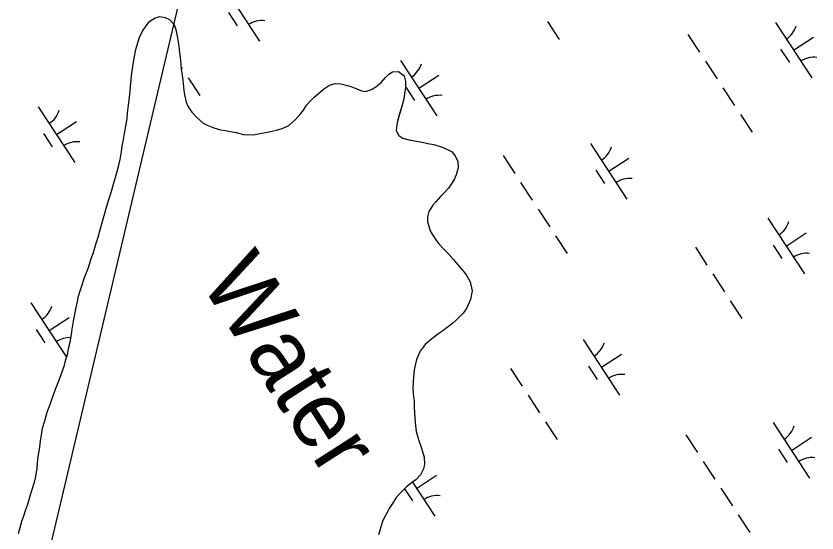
# Model space of a CAD drawing. Extents: x 3945642 to 3966284, y 206476 to 228921.
# Drawn here: x 3961600 to 3962203, y 213839 to 214228 of the extents above; entities that cross this region are included whole.
import ezdxf

# ---------------------------------------------------------------- set-up
doc = ezdxf.new("R2010")
doc.units = 0
for name, color, linetype in [('V-RIVR-IDEN', 7, 'Continuous'), ('V-TOPO-SHOR', 7, 'Continuous'), ('V-UTIL-LINE', 7, 'Continuous'), ('V-WETL-SWMP', 7, 'Continuous')]:
    doc.layers.add(name, color=color, linetype=linetype)

msp = doc.modelspace()

# ---------------------------------------------------------------- linework, layer by layer
at = {"layer": 'V-TOPO-SHOR'}
for points in [[(3961601.81, 213838.43), (3961603.06, 213842.74), (3961604.45, 213847.59), (3961605.55, 213850.95), (3961607.48, 213856.48), (3961608.87, 213860.38), (3961610.67, 213866.58), (3961612.05, 213870.75), (3961613.85, 213877.09), (3961614.83, 213881.13), (3961615.83, 213887.6), (3961616.55, 213894.21), (3961617.98, 213903.66), (3961618.55, 213908.11), (3961619.4, 213914.04), (3961619.97, 213917.68), (3961621.36, 213922.4), (3961622.74, 213926.98), (3961623.71, 213930.48), (3961625.5, 213934.79), (3961626.75, 213938.43), (3961628.82, 213944.21), (3961630.33, 213948.26), (3961632.68, 213954.45), (3961634.33, 213958.62), (3961636.54, 213965.08), (3961637.65, 213969.26), (3961638.76, 213972.9), (3961639.88, 213978.56), (3961640.72, 213982.34), (3961641.71, 213988.14), (3961642.42, 213992.05), (3961643.27, 213997.98), (3961643.98, 214001.89), (3961644.96, 214007.28), (3961646.22, 214012.54), (3961646.92, 214016.18), (3961648.58, 214021.7), (3961649.83, 214025.34), (3961651.63, 214030.86), (3961654.52, 214038.54), (3961656.59, 214045.14), (3961658.25, 214049.71), (3961660.47, 214056.85), (3961661.85, 214061.17), (3961663.66, 214067.9), (3961664.91, 214072.35), (3961666.85, 214079.22), (3961668.23, 214083.8), (3961670.17, 214090.4), (3961671.56, 214094.85), (3961673.36, 214101.05), (3961675.3, 214107.24), (3961677.52, 214115.46), (3961678.37, 214119.77), (3961679.49, 214125.71), (3961679.93, 214129.76), (3961681.05, 214134.88), (3961682.04, 214140.81), (3961682.75, 214144.72), (3961683.6, 214150.52), (3961684.03, 214154.57), (3961684.76, 214160.64), (3961685.33, 214164.69), (3961685.91, 214170.76), (3961686.21, 214174.67), (3961686.66, 214179.26), (3961686.95, 214182.63), (3961687.95, 214189.64), (3961688.94, 214195.98), (3961690.34, 214202.59), (3961692.01, 214208.52), (3961692.98, 214211.61), (3961695.17, 214216.33), (3961697.91, 214220.35), (3961700.9, 214223.71), (3961704.7, 214226.24), (3961708.22, 214227.3), (3961712.4, 214226.59), (3961715.63, 214224.95), (3961719.11, 214221.27), (3961720.43, 214217.48), (3961721.34, 214212.61), (3961722.5, 214204.91), (3961723, 214199.91)], [(3961723, 214199.91), (3961723.52, 214196.53), (3961724.01, 214191.39), (3961724.39, 214188.02), (3961725.03, 214183.02), (3961725.54, 214179.5), (3961726.05, 214174.5), (3961726.43, 214171.39), (3961727.07, 214167.34), (3961728.12, 214162.87), (3961729.44, 214159.89), (3961732.38, 214155.41), (3961736.26, 214151.2), (3961740.82, 214147.11), (3961743.92, 214145.47), (3961749.03, 214143.54), (3961753.88, 214142.15), (3961757.79, 214141.45), (3961762.78, 214140.46), (3961765.75, 214139.9), (3961771.41, 214138.64), (3961778.97, 214138.31), (3961782.48, 214138.96), (3961787.89, 214140), (3961791.54, 214140.78), (3961796.28, 214141.83), (3961800.47, 214143.15), (3961805.35, 214145.4), (3961810.52, 214149.68), (3961814.6, 214154.24), (3961816.51, 214156.8), (3961818.84, 214160.69), (3961821.97, 214164.18), (3961824.42, 214166.73), (3961827.81, 214169.4), (3961831.48, 214172.61), (3961835.96, 214175.55), (3961840.3, 214177), (3961844.62, 214176.56), (3961849.74, 214175.31), (3961852.97, 214174.34), (3961856.6, 214172.82), (3961860.1, 214171.31), (3961863.07, 214170.75), (3961867.81, 214172.33), (3961871.06, 214174.33), (3961874.87, 214177.68), (3961878.14, 214181.44), (3961880.72, 214183.98), (3961883.44, 214185.72), (3961888.03, 214185.82), (3961892.19, 214182.68), (3961893.38, 214178.62), (3961893.2, 214173.62), (3961892.63, 214169.58), (3961892.2, 214166.34), (3961890.81, 214160.68), (3961888.87, 214154.08), (3961886.92, 214147.48), (3961886.2, 214141.54), (3961888.2, 214137.75), (3961891.16, 214135.83), (3961896.01, 214134.45), (3961902.75, 214133.18), (3961907.06, 214132.47), (3961910.03, 214131.77), (3961914.61, 214131.06), (3961921.75, 214128.85), (3961927.81, 214125.7), (3961930.75, 214122.43), (3961932.74, 214118.23), (3961932.84, 214113.37), (3961931.45, 214108.25), (3961929.94, 214104.62), (3961928.3, 214101.93), (3961925.57, 214098.03), (3961922.16, 214094.28), (3961919.58, 214091.87), (3961916.04, 214087.98), (3961913.86, 214085.43), (3961910.85, 214080.59), (3961909.88, 214076.68), (3961909.85, 214072.77), (3961911.82, 214066.14), (3961913.42, 214063.42), (3961916.23, 214059.35), (3961918.5, 214056.36), (3961922.25, 214052.15), (3961925.06, 214049.16), (3961929.07, 214044.67), (3961931.62, 214041.68), (3961934.03, 214038.96), (3961937.37, 214035.02), (3961939.51, 214032.17), (3961941.91, 214027.56), (3961943.61, 214020.93), (3961942.35, 214014.46), (3961940.56, 214010.29), (3961939.19, 214007.6), (3961936.6, 214004.1), (3961931.42, 213998.74)], [(3961931.42, 213998.74), (3961928.84, 213996.6), (3961924.63, 213993.26), (3961921.37, 213990.85), (3961918.39, 213988.85), (3961914.04, 213985.64), (3961911.59, 213983.5), (3961908.2, 213980.56), (3961904.24, 213975.59), (3961901.62, 213969.13), (3961900.79, 213966.03), (3961899.81, 213961.31), (3961899.23, 213956.05), (3961899.07, 213952.54), (3961898.9, 213947.68), (3961899.39, 213941.2), (3961899.77, 213938.09), (3961899.87, 213933.49), (3961899.97, 213929.04), (3961900.45, 213921.75), (3961901.35, 213914.99), (3961903.06, 213909.17), (3961905.3, 213902.67), (3961907.27, 213895.77), (3961907.51, 213890.63), (3961906.94, 213886.99), (3961904.47, 213882.42), (3961901.07, 213878.8), (3961898.62, 213876.93), (3961894.14, 213873.45), (3961889.93, 213869.44), (3961886.38, 213865.41), (3961883.38, 213860.98), (3961880.92, 213857.08), (3961879.55, 213854.26), (3961877.35, 213850.09), (3961875.98, 213847.26), (3961874.74, 213843.36), (3961872.94, 213837.29)]]:
    msp.add_lwpolyline(points, dxfattribs=at)
at = {"layer": 'V-UTIL-LINE'}
msp.add_lwpolyline([(3961854.02, 214793.94), (3961386.17, 212816.75)], dxfattribs=at)
at = {"layer": 'V-WETL-SWMP'}
for p, q in [((3961755.97, 214250.5), (3961783.37, 214208.67)), ((3961704.7, 214226.24), (3961708.22, 214227.3)), ((3961708.22, 214227.3), (3961712.4, 214226.59)), ((3961759.93, 214230.38), (3961766.5, 214220.34)), ((3961697.91, 214220.36), (3961700.9, 214223.71)), ((3961700.9, 214223.71), (3961704.7, 214226.24)), ((3961712.4, 214226.59), (3961715.63, 214224.95)), ((3961715.63, 214224.95), (3961719.11, 214221.27)), ((3961719.11, 214221.27), (3961720.43, 214217.48)), ((3962000.3, 214223.43), (3962009.07, 214210.05)), ((3962171.77, 214222.88), (3962199.16, 214181.06)), ((3961692.98, 214211.62), (3961695.18, 214216.33)), ((3961695.18, 214216.33), (3961697.91, 214220.36)), ((3961720.43, 214217.48), (3961721.34, 214212.61)), ((3961692.01, 214208.52), (3961692.98, 214211.62)), ((3961721.34, 214212.61), (3961722.5, 214204.91)), ((3962105.97, 214213.76), (3962114.74, 214200.37)), ((3962185.46, 214201.97), (3962200.52, 214211.83)), ((3961690.34, 214202.59), (3961692.01, 214208.52)), ((3961722.5, 214204.91), (3961723, 214199.91)), ((3962175.72, 214202.76), (3962182.3, 214192.72)), ((3961688.94, 214195.98), (3961690.34, 214202.59)), ((3961723, 214199.91), (3961723.51, 214196.53)), ((3961687.95, 214189.65), (3961688.94, 214195.98)), ((3961723.51, 214196.53), (3961724.01, 214191.39)), ((3961724.01, 214191.39), (3961724.39, 214188.02)), ((3961889.55, 214194.27), (3961916.95, 214152.45)), ((3962119.12, 214193.68), (3962127.89, 214180.3)), ((3961686.95, 214182.63), (3961687.95, 214189.65)), ((3961724.24, 214189.37), (3961725.24, 214187.84)), ((3961724.39, 214188.02), (3961725.03, 214183.02)), ((3961880.72, 214183.98), (3961883.44, 214185.72)), ((3961883.44, 214185.72), (3961888.03, 214185.82)), ((3961888.03, 214185.82), (3961892.19, 214182.68)), ((3961686.21, 214174.67), (3961686.65, 214179.26)), ((3961686.65, 214179.26), (3961686.95, 214182.63)), ((3961725.03, 214183.02), (3961725.54, 214179.5)), ((3961725.54, 214179.5), (3961726.04, 214174.5)), ((3961729.63, 214181.15), (3961738.4, 214167.76)), ((3961874.87, 214177.68), (3961878.14, 214181.44)), ((3961878.14, 214181.44), (3961880.72, 214183.98)), ((3961892.19, 214182.68), (3961893.38, 214178.62)), ((3961893.38, 214178.62), (3961893.2, 214173.62)), ((3961903.25, 214173.36), (3961918.31, 214183.22)), ((3961685.91, 214170.76), (3961686.21, 214174.67)), ((3961726.04, 214174.5), (3961726.43, 214171.39)), ((3961827.82, 214169.4), (3961831.49, 214172.61)), ((3961831.49, 214172.61), (3961835.96, 214175.55)), ((3961835.96, 214175.55), (3961840.3, 214177)), ((3961840.3, 214177), (3961844.61, 214176.56)), ((3961844.61, 214176.56), (3961849.74, 214175.31)), ((3961849.74, 214175.31), (3961852.97, 214174.34)), ((3961852.97, 214174.34), (3961856.6, 214172.83)), ((3961856.6, 214172.83), (3961860.1, 214171.31)), ((3961867.81, 214172.33), (3961871.06, 214174.33)), ((3961871.06, 214174.33), (3961874.87, 214177.68)), ((3961893.2, 214173.62), (3961892.63, 214169.58)), ((3961893.51, 214174.15), (3961900.09, 214164.11)), ((3962132.27, 214173.6), (3962141.04, 214160.22)), ((3961685.33, 214164.69), (3961685.91, 214170.76)), ((3961726.43, 214171.39), (3961727.07, 214167.34)), ((3961727.07, 214167.34), (3961728.12, 214162.87)), ((3961821.97, 214164.18), (3961824.42, 214166.73)), ((3961824.42, 214166.73), (3961827.82, 214169.4)), ((3961860.1, 214171.31), (3961863.07, 214170.75)), ((3961863.07, 214170.75), (3961867.81, 214172.33)), ((3961892.63, 214169.58), (3961892.2, 214166.34)), ((3961684.03, 214154.57), (3961684.76, 214160.64)), ((3961684.76, 214160.64), (3961685.33, 214164.69)), ((3961728.12, 214162.87), (3961729.44, 214159.89)), ((3961816.51, 214156.79), (3961818.84, 214160.69)), ((3961818.84, 214160.69), (3961821.97, 214164.18)), ((3961890.81, 214160.68), (3961886.93, 214147.48)), ((3961892.2, 214166.34), (3961890.81, 214160.68)), ((3961616.83, 214159.35), (3961644.23, 214117.52)), ((3961683.6, 214150.52), (3961684.03, 214154.57)), ((3961729.44, 214159.89), (3961732.38, 214155.41)), ((3961732.38, 214155.41), (3961736.26, 214151.2)), ((3961814.6, 214154.24), (3961816.51, 214156.79)), ((3961682.74, 214144.72), (3961683.6, 214150.52)), ((3961736.26, 214151.2), (3961740.82, 214147.11)), ((3961805.35, 214145.4), (3961810.52, 214149.68)), ((3961810.52, 214149.68), (3961814.6, 214154.24)), ((3962145.43, 214153.53), (3962154.19, 214140.15)), ((3961630.53, 214138.43), (3961645.58, 214148.3)), ((3961682.04, 214140.81), (3961682.74, 214144.72)), ((3961740.82, 214147.11), (3961743.92, 214145.47)), ((3961743.92, 214145.47), (3961749.03, 214143.54)), ((3961749.03, 214143.54), (3961753.88, 214142.15)), ((3961796.28, 214141.83), (3961800.48, 214143.14)), ((3961800.48, 214143.14), (3961805.35, 214145.4)), ((3961886.93, 214147.48), (3961886.2, 214141.54)), ((3961620.79, 214139.22), (3961627.36, 214129.19)), ((3961681.05, 214134.88), (3961682.04, 214140.81)), ((3961753.88, 214142.15), (3961757.79, 214141.45)), ((3961757.79, 214141.45), (3961762.78, 214140.46)), ((3961762.78, 214140.46), (3961765.75, 214139.9)), ((3961765.75, 214139.9), (3961771.41, 214138.64)), ((3961771.41, 214138.64), (3961778.97, 214138.31)), ((3961778.97, 214138.31), (3961782.48, 214138.96)), ((3961782.48, 214138.96), (3961787.89, 214140)), ((3961787.89, 214140), (3961791.54, 214140.78)), ((3961791.54, 214140.78), (3961796.28, 214141.83)), ((3961886.2, 214141.54), (3961888.2, 214137.75)), ((3961888.2, 214137.75), (3961891.16, 214135.83)), ((3961679.93, 214129.76), (3961681.05, 214134.88)), ((3961891.16, 214135.83), (3961896.01, 214134.45)), ((3961896.01, 214134.45), (3961902.75, 214133.18)), ((3961902.75, 214133.18), (3961907.06, 214132.47)), ((3961907.06, 214132.47), (3961910.03, 214131.77)), ((3961910.03, 214131.77), (3961914.61, 214131.06)), ((3961914.61, 214131.06), (3961921.75, 214128.85)), ((3962032.63, 214131.73), (3962060.03, 214089.9)), ((3961678.37, 214119.77), (3961679.49, 214125.71)), ((3961679.49, 214125.71), (3961679.93, 214129.76)), ((3961921.75, 214128.85), (3961927.81, 214125.7)), ((3961927.81, 214125.7), (3961930.75, 214122.43)), ((3961677.52, 214115.46), (3961678.37, 214119.77)), ((3961930.75, 214122.43), (3961932.75, 214118.23)), ((3961966.83, 214122.6), (3961975.6, 214109.22)), ((3962046.33, 214110.82), (3962061.38, 214120.68)), ((3961675.3, 214107.24), (3961677.52, 214115.46)), ((3961932.84, 214113.37), (3961931.45, 214108.25)), ((3961932.75, 214118.23), (3961932.84, 214113.37)), ((3961673.36, 214101.05), (3961675.3, 214107.24)), ((3961931.45, 214108.25), (3961929.94, 214104.61)), ((3962036.58, 214111.61), (3962043.16, 214101.57)), ((3961671.56, 214094.85), (3961673.36, 214101.05)), ((3961928.3, 214101.93), (3961925.57, 214098.03)), ((3961929.94, 214104.61), (3961928.3, 214101.93)), ((3961979.98, 214102.53), (3961988.75, 214089.15)), ((3961670.18, 214090.4), (3961671.56, 214094.85)), ((3961922.16, 214094.28), (3961919.58, 214091.87)), ((3961925.57, 214098.03), (3961922.16, 214094.28)), ((3961668.23, 214083.8), (3961670.18, 214090.4)), ((3961919.58, 214091.87), (3961916.04, 214087.98)), ((3961666.85, 214079.22), (3961668.23, 214083.8)), ((3961913.86, 214085.43), (3961910.85, 214080.59)), ((3961916.04, 214087.98), (3961913.86, 214085.43)), ((3961993.14, 214082.45), (3962001.9, 214069.07)), ((3961664.91, 214072.35), (3961666.85, 214079.22)), ((3961909.88, 214076.68), (3961909.85, 214072.77)), ((3961910.85, 214080.59), (3961909.88, 214076.68)), ((3961663.66, 214067.9), (3961664.91, 214072.35)), ((3961909.85, 214072.77), (3961911.82, 214066.14)), ((3962166.21, 214075.5), (3962193.61, 214033.68)), ((3961661.85, 214061.17), (3961663.66, 214067.9)), ((3961911.82, 214066.14), (3961913.42, 214063.42)), ((3962179.91, 214054.59), (3962194.97, 214064.45)), ((3961660.47, 214056.86), (3961661.85, 214061.17)), ((3961913.42, 214063.42), (3961916.23, 214059.35)), ((3961916.23, 214059.35), (3961918.5, 214056.36)), ((3962006.29, 214062.38), (3962015.06, 214048.99)), ((3961658.25, 214049.71), (3961660.47, 214056.86)), ((3961918.5, 214056.36), (3961922.25, 214052.15)), ((3961922.25, 214052.15), (3961925.06, 214049.16)), ((3962111.52, 214053.67), (3962120.29, 214040.28)), ((3962170.17, 214055.38), (3962176.75, 214045.34)), ((3961656.6, 214045.14), (3961658.25, 214049.71)), ((3961925.06, 214049.16), (3961929.08, 214044.67)), ((3961654.52, 214038.54), (3961656.6, 214045.14)), ((3961929.08, 214044.67), (3961931.62, 214041.68)), ((3961931.62, 214041.68), (3961934.03, 214038.96)), ((3961651.62, 214030.86), (3961654.52, 214038.54)), ((3961934.03, 214038.96), (3961937.37, 214035.02)), ((3961937.37, 214035.02), (3961939.51, 214032.17)), ((3961649.83, 214025.34), (3961651.62, 214030.86)), ((3961939.51, 214032.17), (3961941.91, 214027.56)), ((3962124.67, 214033.59), (3962133.44, 214020.21)), ((3961648.58, 214021.7), (3961649.83, 214025.34)), ((3961941.91, 214027.56), (3961943.61, 214020.93)), ((3961646.22, 214012.54), (3961646.92, 214016.18)), ((3961646.92, 214016.18), (3961648.58, 214021.7)), ((3961943.61, 214020.93), (3961942.35, 214014.46)), ((3961611.28, 214011.97), (3961638.16, 213970.93)), ((3961644.96, 214007.28), (3961646.22, 214012.54)), ((3961940.56, 214010.29), (3961939.19, 214007.6)), ((3961942.35, 214014.46), (3961940.56, 214010.29)), ((3962137.82, 214013.51), (3962146.59, 214000.13)), ((3961643.98, 214001.89), (3961644.96, 214007.28)), ((3961936.6, 214004.1), (3961931.42, 213998.74)), ((3961939.19, 214007.6), (3961936.6, 214004.1)), ((3961624.98, 213991.06), (3961640.03, 214000.92)), ((3961642.42, 213992.05), (3961643.27, 213997.98)), ((3961643.27, 213997.98), (3961643.98, 214001.89)), ((3961931.42, 213998.74), (3961928.84, 213996.6)), ((3961615.23, 213991.85), (3961621.81, 213981.81)), ((3961641.71, 213988.14), (3961642.42, 213992.05)), ((3961924.63, 213993.26), (3961921.37, 213990.85)), ((3961928.84, 213996.6), (3961924.63, 213993.26)), ((3961640.72, 213982.34), (3961641.71, 213988.14)), ((3961914.04, 213985.64), (3961911.59, 213983.5)), ((3961918.39, 213988.85), (3961914.04, 213985.64)), ((3961921.37, 213990.85), (3961918.39, 213988.85)), ((3961639.88, 213978.56), (3961640.72, 213982.34)), ((3961908.2, 213980.56), (3961904.24, 213975.59)), ((3961911.59, 213983.5), (3961908.2, 213980.56)), ((3962027.07, 213984.35), (3962054.47, 213942.53)), ((3961638.76, 213972.9), (3961639.88, 213978.56)), ((3961904.24, 213975.59), (3961901.63, 213969.13)), ((3961636.54, 213965.08), (3961637.65, 213969.26)), ((3961637.65, 213969.26), (3961638.76, 213972.9)), ((3961901.63, 213969.13), (3961900.79, 213966.03)), ((3962040.77, 213963.44), (3962055.83, 213973.3)), ((3961634.33, 213958.62), (3961636.54, 213965.08)), ((3961900.79, 213966.03), (3961899.81, 213961.31)), ((3961972.38, 213962.51), (3961981.15, 213949.13)), ((3962031.03, 213964.23), (3962037.61, 213954.19)), ((3961632.68, 213954.45), (3961634.33, 213958.62)), ((3961899.23, 213956.05), (3961899.07, 213952.54)), ((3961899.81, 213961.31), (3961899.23, 213956.05)), ((3961630.33, 213948.25), (3961632.68, 213954.45)), ((3961899.07, 213952.54), (3961898.9, 213947.68)), ((3961626.75, 213938.43), (3961628.82, 213944.21)), ((3961628.82, 213944.21), (3961630.33, 213948.25)), ((3961898.9, 213947.68), (3961899.39, 213941.2)), ((3961625.5, 213934.79), (3961626.75, 213938.43)), ((3961899.39, 213941.2), (3961899.77, 213938.09)), ((3961899.77, 213938.09), (3961899.87, 213933.5)), ((3961985.53, 213942.44), (3961994.3, 213929.05)), ((3961623.72, 213930.48), (3961625.5, 213934.79)), ((3961899.87, 213933.5), (3961899.97, 213929.04)), ((3961621.36, 213922.4), (3961622.74, 213926.98)), ((3961622.74, 213926.98), (3961623.72, 213930.48)), ((3961899.97, 213929.04), (3961900.45, 213921.74)), ((3961619.97, 213917.68), (3961621.36, 213922.4)), ((3961900.45, 213921.74), (3961901.35, 213914.99)), ((3961998.68, 213922.36), (3962007.45, 213908.98)), ((3962170.15, 213921.81), (3962197.55, 213879.99)), ((3961618.55, 213908.11), (3961619.4, 213914.04)), ((3961619.4, 213914.04), (3961619.97, 213917.68)), ((3961901.35, 213914.99), (3961903.06, 213909.17)), ((3961617.97, 213903.66), (3961618.55, 213908.11)), ((3961903.06, 213909.17), (3961905.3, 213902.67)), ((3962104.35, 213912.69), (3962113.12, 213899.3)), ((3962183.85, 213900.9), (3962198.9, 213910.76)), ((3961616.55, 213894.21), (3961617.97, 213903.66)), ((3961905.3, 213902.67), (3961907.27, 213895.77)), ((3962174.1, 213901.69), (3962180.68, 213891.65)), ((3961907.27, 213895.77), (3961907.51, 213890.63)), ((3961615.83, 213887.6), (3961616.55, 213894.21)), ((3961907.51, 213890.63), (3961906.94, 213886.99)), ((3962117.5, 213892.61), (3962126.27, 213879.23)), ((3961614.83, 213881.13), (3961615.83, 213887.6)), ((3961906.94, 213886.99), (3961904.47, 213882.42)), ((3961612.05, 213870.75), (3961613.85, 213877.09)), ((3961613.85, 213877.09), (3961614.83, 213881.13)), ((3961901.07, 213878.8), (3961898.62, 213876.93)), ((3961904.47, 213882.42), (3961901.07, 213878.8)), ((3961901.63, 213872.29), (3961916.69, 213882.15)), ((3961894.14, 213873.45), (3961889.93, 213869.43)), ((3961892.61, 213871.99), (3961898.47, 213863.04)), ((3961898.62, 213876.93), (3961894.14, 213873.45)), ((3961898.6, 213876.91), (3961915.33, 213851.38)), ((3962130.66, 213872.53), (3962139.42, 213859.15)), ((3961608.87, 213860.38), (3961610.67, 213866.58)), ((3961610.67, 213866.58), (3961612.05, 213870.75)), ((3961886.38, 213865.41), (3961883.38, 213860.98)), ((3961889.93, 213869.43), (3961886.38, 213865.41)), ((3961607.48, 213856.48), (3961608.87, 213860.38)), ((3961883.38, 213860.98), (3961880.92, 213857.08)), ((3961605.55, 213850.96), (3961607.48, 213856.48)), ((3961879.55, 213854.26), (3961877.35, 213850.09)), ((3961880.92, 213857.08), (3961879.55, 213854.26)), ((3961603.06, 213842.74), (3961604.45, 213847.59)), ((3961604.45, 213847.59), (3961605.55, 213850.96)), ((3961875.98, 213847.26), (3961874.74, 213843.36)), ((3961877.35, 213850.09), (3961875.98, 213847.26)), ((3962143.81, 213852.46), (3962152.58, 213839.07)), ((3961601.81, 213838.43), (3961603.06, 213842.74)), ((3961874.74, 213843.36), (3961872.94, 213837.29))]:
    msp.add_line(p, q, dxfattribs=at)
for centre, start, end in [((3961785, 214206.61), 82.45745, 124.00111), ((3962170.53, 214225.2), 302.45745, 344.00111), ((3961888.31, 214196.59), 302.45745, 344.00111), ((3962200.8, 214178.99), 82.45745, 124.00111), ((3961918.59, 214150.38), 82.45745, 124.00111), ((3961615.59, 214161.67), 302.45745, 344.00111), ((3961645.86, 214115.46), 82.45745, 124.00111), ((3962031.39, 214134.05), 302.45745, 344.00111), ((3962061.66, 214087.84), 82.45745, 124.00111), ((3962164.97, 214077.83), 302.45745, 344.00111), ((3962195.25, 214031.62), 82.45745, 124.00111), ((3961610.04, 214014.29), 302.45745, 344.00111), ((3961640.31, 213968.08), 86.80829, 124.00111), ((3962025.84, 213986.67), 302.45745, 344.00111), ((3962056.11, 213940.46), 82.45745, 124.00111), ((3962168.91, 213924.13), 302.45745, 344.00111), ((3962199.18, 213877.92), 82.45745, 124.00111), ((3961916.97, 213849.31), 82.45745, 124.00111)]:
    msp.add_arc(centre, 17.62, start, end, dxfattribs=at)

# ---------------------------------------------------------------- texts
at = {"layer": 'V-RIVR-IDEN'}
msp.add_text('Water', height=50, rotation=302.67566, dxfattribs=at).set_placement((3961737.81, 214028.1))

doc.saveas('drawing.dxf')
